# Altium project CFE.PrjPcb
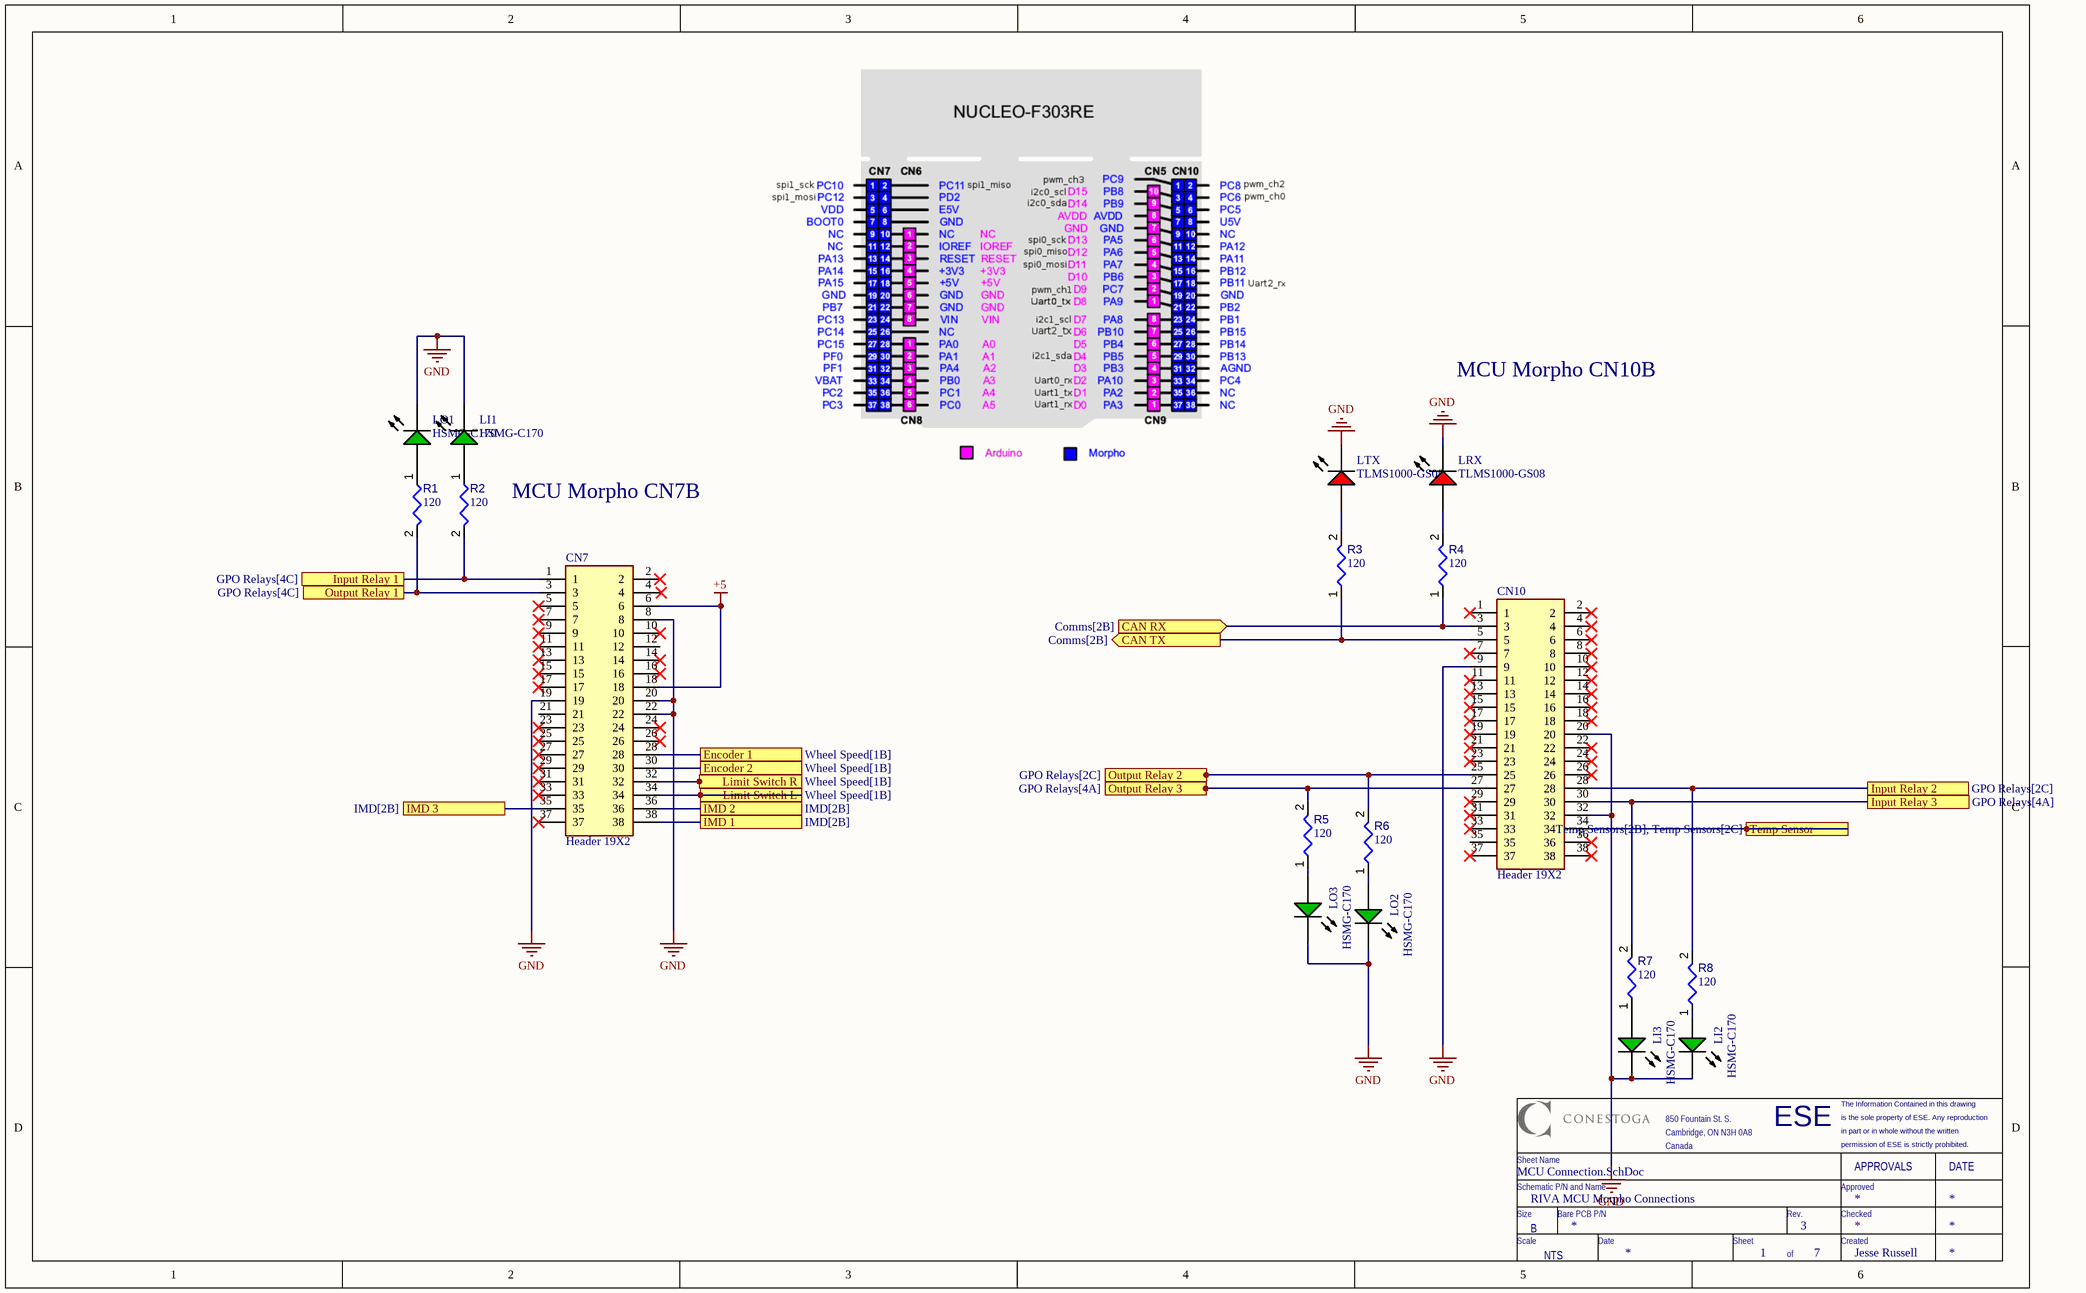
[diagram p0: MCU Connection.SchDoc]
7 sheets, 58 parts. Net scope: flat (ports and power ports of the same name join across sheets).
Board file: STM32 Sheild.PcbDoc
Sheets:
  MCU Connection.SchDoc
  Comms.SchDoc
  Power.SchDoc
  Temp Sensors.SchDoc
  GPO Relays.SchDoc
  Wheel Speed.SchDoc
  IMD.SchDoc

## Sheet MCU Connection.SchDoc: RIVA MCU Morpho Connections
size B; Engineer: Jesse Russell; Revision: 3; SheetNumber: 1; SheetTotal: 7

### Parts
CN7  Header 19X2  [2*19P]
CN10  Header 19X2  [2*19P]
LI1  HSMG-C170  [AVAG-HSMX-C170_V]
LI2  HSMG-C170  [AVAG-HSMX-C170_V]
LI3  HSMG-C170  [AVAG-HSMX-C170_V]
LO1  HSMG-C170  [AVAG-HSMX-C170_V]
LO2  HSMG-C170  [AVAG-HSMX-C170_V]
LO3  HSMG-C170  [AVAG-HSMX-C170_V]
LRX  TLMS1000-GS08  [VISH-TLMS1000_V]
LTX  TLMS1000-GS08  [VISH-TLMS1000_V]
R1  value 120  [RESC0603(1608)_L]  (hidden comment: Resistor 120R +/-5 % 0603 0.1 W)
R2  value 120  [RESC0603(1608)_L]  (hidden comment: Resistor 120R +/-5 % 0603 0.1 W)
R3  value 120  [RESC0603(1608)_L]  (hidden comment: Resistor 120R +/-5 % 0603 0.1 W)
R4  value 120  [RESC0603(1608)_L]  (hidden comment: Resistor 120R +/-5 % 0603 0.1 W)
R5  value 120  [RESC0603(1608)_L]  (hidden comment: Resistor 120R +/-5 % 0603 0.1 W)
R6  value 120  [RESC0603(1608)_L]  (hidden comment: Resistor 120R +/-5 % 0603 0.1 W)
R7  value 120  [RESC0603(1608)_L]  (hidden comment: Resistor 120R +/-5 % 0603 0.1 W)
R8  value 120  [RESC0603(1608)_L]  (hidden comment: Resistor 120R +/-5 % 0603 0.1 W)

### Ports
CAN RX (in, see Comms[2B]), CAN TX (out, see Comms[2B]), Encoder 1 (see Wheel Speed[1B]), Encoder 2 (see Wheel Speed[1B]), IMD 1 (see IMD[2B]), IMD 2 (see IMD[2B]), IMD 3 (see IMD[2B]), Input Relay 1 (see GPO Relays[4C]), Input Relay 2 (see GPO Relays[2C]), Input Relay 3 (see GPO Relays[4A]), Limit Switch L (see Wheel Speed[1B]), Limit Switch R (see Wheel Speed[1B]), Output Relay 1 (see GPO Relays[4C]), Output Relay 2 (see GPO Relays[2C]), Output Relay 3 (see GPO Relays[4A]), Temp Sensor (see Temp Sensors[2B], Temp Sensors[2C])

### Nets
+5: CN7.6 CN7.18
GND: CN7.8 CN7.19 CN7.20 CN7.22 CN10.9 CN10.20 CN10.32 LI1.2(K) LI2.2(K) LI3.2(K) LO1.2(K) LO2.2(K) LO3.2(K) LRX.2(K) LTX.2(K)
NetCN7_1: CN7.1 R2.2 ; port Input Relay 1
NetCN7_3: CN7.3 R1.2 ; port Output Relay 1
NetCN7_28: CN7.28 ; port Encoder 1
NetCN7_30: CN7.30 ; port Encoder 2
NetCN7_32: CN7.32 ; port Limit Switch R
NetCN7_34: CN7.34 ; port Limit Switch L
NetCN7_35: CN7.35 ; port IMD 3
NetCN7_36: CN7.36 ; port IMD 2
NetCN7_38: CN7.38 ; port IMD 1
NetCN10_3: CN10.3 R4.1 ; port CAN RX
NetCN10_5: CN10.5 R3.1 ; port CAN TX
NetCN10_25: CN10.25 R6.2 ; port Output Relay 2
NetCN10_27: CN10.27 R5.2 ; port Output Relay 3
NetCN10_28: CN10.28 R8.2 ; port Input Relay 2
NetCN10_30: CN10.30 R7.2 ; port Input Relay 3
NetCN10_34: CN10.34 ; port Temp Sensor
NetLI1_1: LI1.1(A) R2.1
NetLI2_1: LI2.1(A) R8.1
NetLI3_1: LI3.1(A) R7.1
NetLO1_1: LO1.1(A) R1.1
NetLO2_1: LO2.1(A) R6.1
NetLO3_1: LO3.1(A) R5.1
NetLRX_1: LRX.1(A) R4.2
NetLTX_1: LTX.1(A) R3.2

Not connected (* = marked no-connect by the designer): CN7 2* 4 5* 7* 9* 10* 11* 12 13* 14* 15* 16* 17* 21 23* 24* 25* 26* 27* 29* 31* 33* 37*; CN10 1* 2* 4* 6* 7* 8* 10* 11* 12* 13* 14* 15* 16* 17* 18* 19* 21* 22* 23* 24* 26* 29* 31* 33* 35 36* 37* 38*

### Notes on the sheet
- MCU Morpho CN10B
- MCU Morpho CN7B

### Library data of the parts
CN7 CN10 = SSW-119-01-T-D: Connector; Manufacturer_Name: SAMTEC
LI1-LI3 LO1-LO3 = CMP-2000-05062-1: Chip LED, Green, 2.2 V, -40 to 85 degC, 2-Pin SMD, Pb-Free, Tape and Reel; Manufacturer: Avago; No. of Pins: 2; Peak Wavelength: 570nm; SVHC: NoSVHC(16-Jun-2014); Dominant Wavelength: 572nm; Forward Current If: 20mA; Viewing Angle: 170deg; Lens Shape: Rectangular; PIV Max: 5V; External Width: 1.25mm; LED Type: Standard; External Depth: 0.8mm; Opto Mounting Orientation: Top; Luminous Intensity: 15mcd; Luminous Intensity Min: 4mcd; Forward Voltage VF Max: 2.6V; External Length / Height: 2mm; Bulb Size: 1.25mmx1.4mm; Light Area Height: 1mm; Voltage Vf Typ: 2.2V
LRX LTX = CMP-2000-07254-1: Low Current LED, 40 mW, 1.8 V, -40 to 100 degC, 2-Pin SMD (0603), RoHS, Tape and Reel; Manufacturer: Vishay; Lens Shape: Rectangular; Automotive Qualification Standard: AEC-Q100; Wavelength Typ: 636nm; SVHC: ToBeAdvised; LED Colour: Red; Bulb Size: 1.6mmx0.8mm; Forward Voltage: 1.8V; Luminous Intensity: 4mcd; Forward Current If: 2mA; Viewing Angle: 80°
R1-R8 = CMP-009-00176-3: Chip Resistor, 120 Ohms, +/-5 %, 0.1 W, -55 to 155 degC, 0603; Power: 100mW; Tolerance: 5%

## Sheet Comms.SchDoc: Communication (R-Pi, RS232, CANBUS)
size B; Engineer: Jesse Russell; Organization: Conestoga Collage; Revision: 4; SheetNumber: 2; SheetTotal: 7
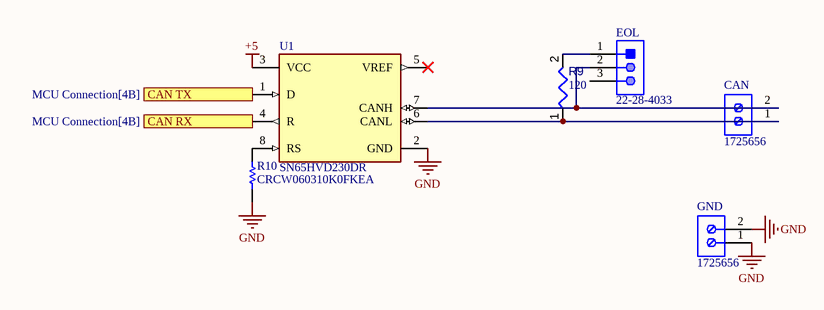
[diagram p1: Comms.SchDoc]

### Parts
CAN  1725656  [PHOE-1725656-2]
EOL  22-28-4033  [MOLX-22-28-4033_V]
GND  1725656  [PHOE-1725656-2]
R9  value 120  [RESC0603(1608)_L]  (hidden comment: Resistor 120R +/-5 % 0603 0.1 W)
R10  CRCW060310K0FKEA  [RESC1609X50X30NL8T20]
U1  SN65HVD230DR  [FP-D0008A-IPC_A]

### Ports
CAN RX (in, see MCU Connection[4B]), CAN TX (out, see MCU Connection[4B])

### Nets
+5: U1.3(VCC)
GND: GND.1 GND.2 R10.1 U1.2(GND)
NetCAN_1: CAN.1 R9.1 U1.6(CANL)
NetCAN_2: CAN.2 EOL.2 U1.7(CANH)
NetCN10_3: U1.4(R) ; port CAN RX
NetCN10_5: U1.1(D) ; port CAN TX
NetEOL_1: EOL.1 R9.2
NetR10_2: R10.2 U1.8(RS)

Not connected (* = marked no-connect by the designer): EOL 3; U1 5(VREF)*

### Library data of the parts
CAN GND = CMP-2000-05299-1: Male Header, Pitch 2.54 mm, 1 x 2 Position, Height 9 mm, Tail Length 3.5 mm; Manufacturer: Phoenix Contact; Number of contacts: 2; Content: 250pc(s); Pitch: 2.54mm; Industrial packaging: Yes
EOL = CMP-1676-00001-5: Male Header, Pitch 2.54 mm, 1 x 3 Position, Height 8.38 mm, Tail Length 3.18 mm, RoHS, Bulk; Manufacturer: Molex; Rows: 1; Voltage Rating: 250 V; Current Rating: 4 A
R9 = CMP-009-00176-3: as R1 on sheet MCU Connection
R10 = CMP-1666-00005-4: Chip Resistor, 10 KOhm, +/- 1%, 100 mW, -55 to 155 degC, 0603 (1608 Metric), RoHS, Tape and Reel; Manufacturer: Vishay Semiconductor; Voltage Rating: 75 V
U1 = CMP-0315-00015-3: IC TRANSCEIVER HALF 1/1 8SOIC; Number of Transceivers: 1; Operating Supply Voltage: 3.3V; Number of I/Os: 2; Max Supply Current: 17mA; Max Supply Voltage: 3.6V; Min Supply Voltage: 3V; Data Rate: 1Mbps

## Sheet Power.SchDoc
size A4; SheetNumber: 3; SheetTotal: 7
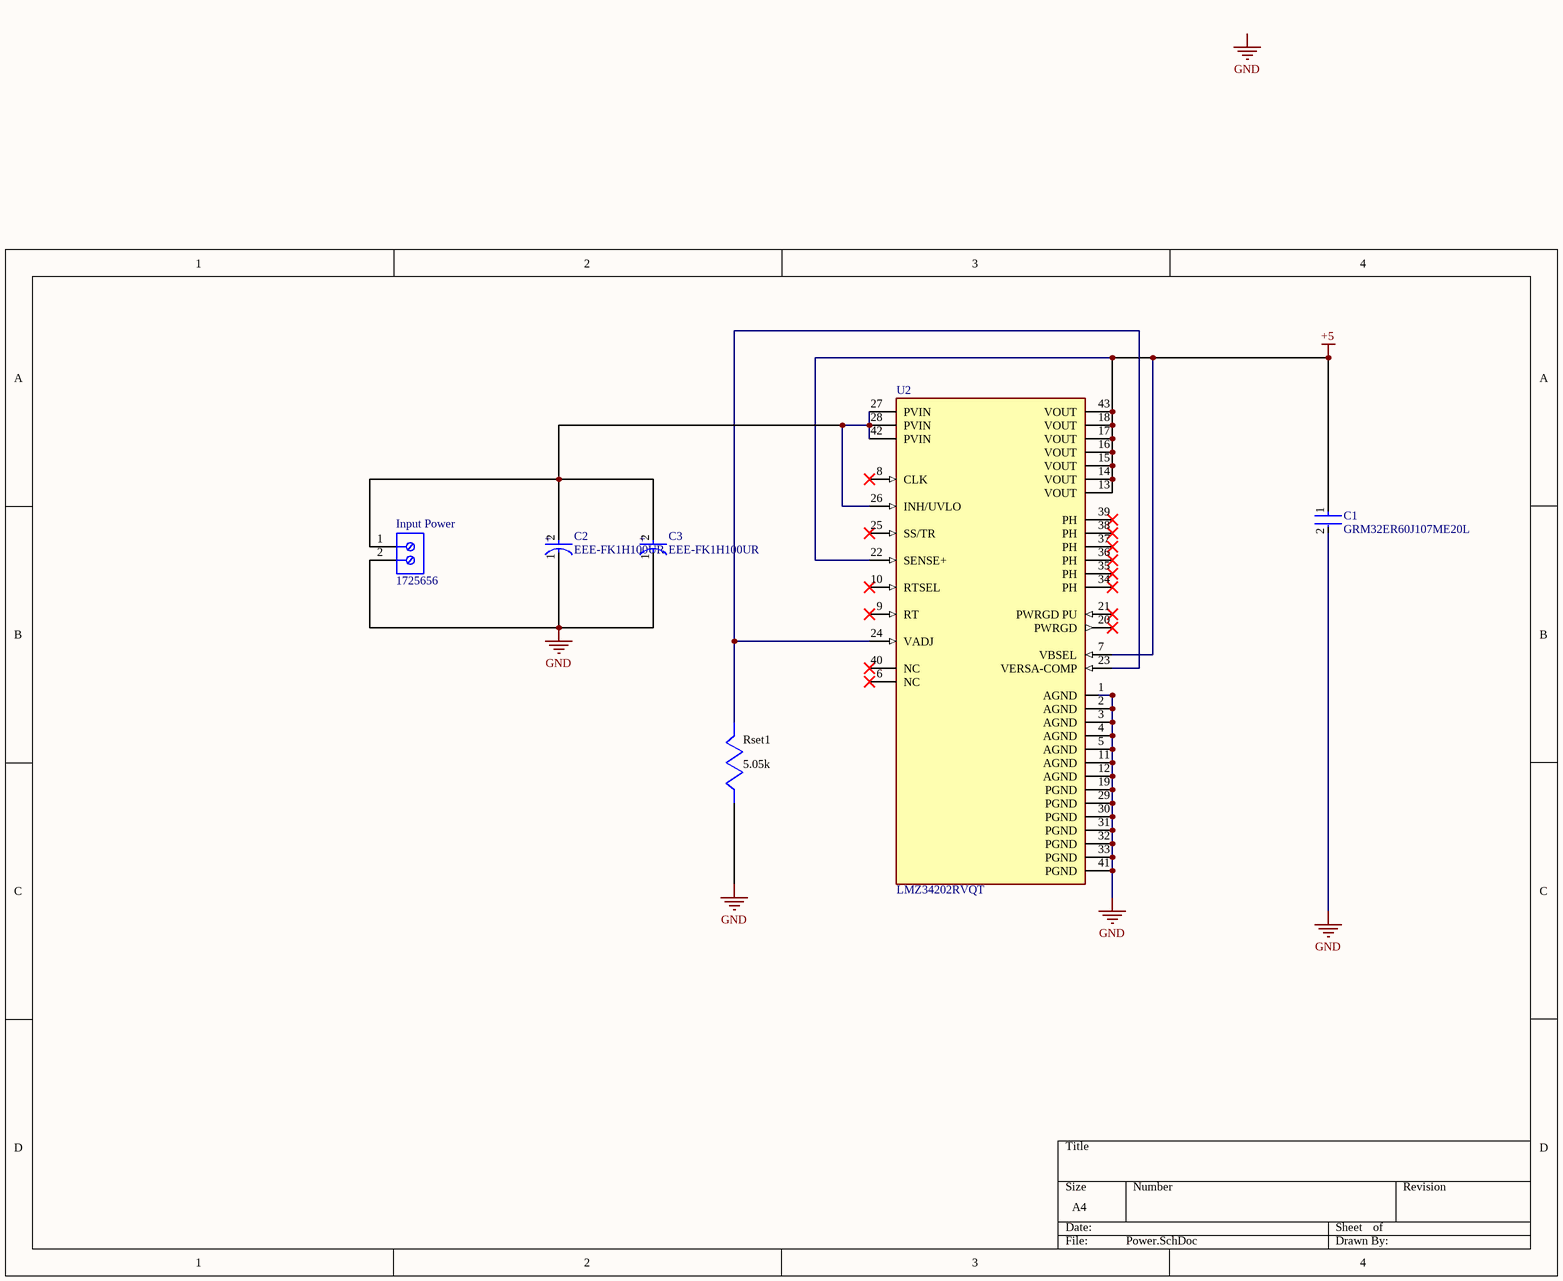
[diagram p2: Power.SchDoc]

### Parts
C1  GRM32ER60J107ME20L  [FP-GRM32-0_3-MFG]
C2  EEE-FK1H100UR  [FP-FKC-MFG]
C3  EEE-FK1H100UR  [FP-FKC-MFG]
Input_Power  1725656  [PHOE-1725656-2]
Rset1  value 5.05k  (hidden comment: CUSTOM1)
U2  LMZ34202RVQT  [FP-RVQ0043E-MFG]

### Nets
+5: C1.1 U2.7(VBSEL) U2.13(VOUT) U2.14(VOUT) U2.15(VOUT) U2.16(VOUT) U2.17(VOUT) U2.18(VOUT) U2.22(SENSE+) U2.43(VOUT)
GND: C1.2 C2.1(C) C3.1(C) Input_Power.2 Rset1.1 U2.1(AGND) U2.2(AGND) U2.3(AGND) U2.4(AGND) U2.5(AGND) U2.11(AGND) U2.12(AGND) U2.19(PGND) U2.29(PGND) U2.30(PGND) U2.31(PGND) U2.32(PGND) U2.33(PGND) U2.41(PGND)
NetC2_2: C2.2(A) C3.2(A) Input_Power.1 U2.26(INH/UVLO) U2.27(PVIN) U2.28(PVIN) U2.42(PVIN)
NetRset1_2: Rset1.2 U2.23(VERSA-COMP) U2.24(VADJ)

Not connected (* = marked no-connect by the designer): U2 6(NC)* 8(CLK)* 9(RT)* 10(RTSEL)* 20(PWRGD)* 21(PWRGD_PU)* 25(SS/TR)* 34(PH)* 35(PH)* 36(PH)* 37(PH)* 38(PH)* 39(PH)* 40(NC)*

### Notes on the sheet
- Labels drawn without touching a wire or pin: GND

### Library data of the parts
C1 = CMP-2000-05259-2: CAP CER 100UF 6.3V X5R 1210; 3DS Part Number: 220-00002; Manufacturer: Murata; Description: Chip Multilayer Ceramic Capacitors for General; Temperature Coefficient: 15%; Material: Ceramic; Tolerance: 20%
C2 C3 = CMP-05427-000030-1: CAP ALUM 10UF 20% 50V SMD; Impedance: 1.52R; Ripple Current (AC): 85mA; Life (Hours): 2000Hour; Leakage Current: 3uA; Dielectric Material: Aluminium
Input_Power = CMP-2000-05299-1: as CAN on sheet Comms
Rset1 = CUSTOM1: Manufacturer Name: CUSTOM
U2 = CMP-04918-000024-1: DC DC CONVERTER 2.5-7.5V 2A; Manufacturer: Texas Instruments; Output Type: AdjustableProgrammable; Max Junction Temp: +125°C; Max Duty Cycle: 90%; Min Supply Voltage: 4.5V; Switching Frequency: 300-1000kHz; Nominal Supply Current: 0.6mA; Max Supply Voltage: 42V; Switching Topology: Buck,Buck-Boost; Standoff Height: 0mm; Description: Non-Isolated PoL Module DC DC Converter 1 Output 2.5 ~ 7.5V    2A 4.5V - 42V Input; Number Of Outputs: 1

## Sheet Temp Sensors.SchDoc
size A4; SheetNumber: 4; SheetTotal: 7
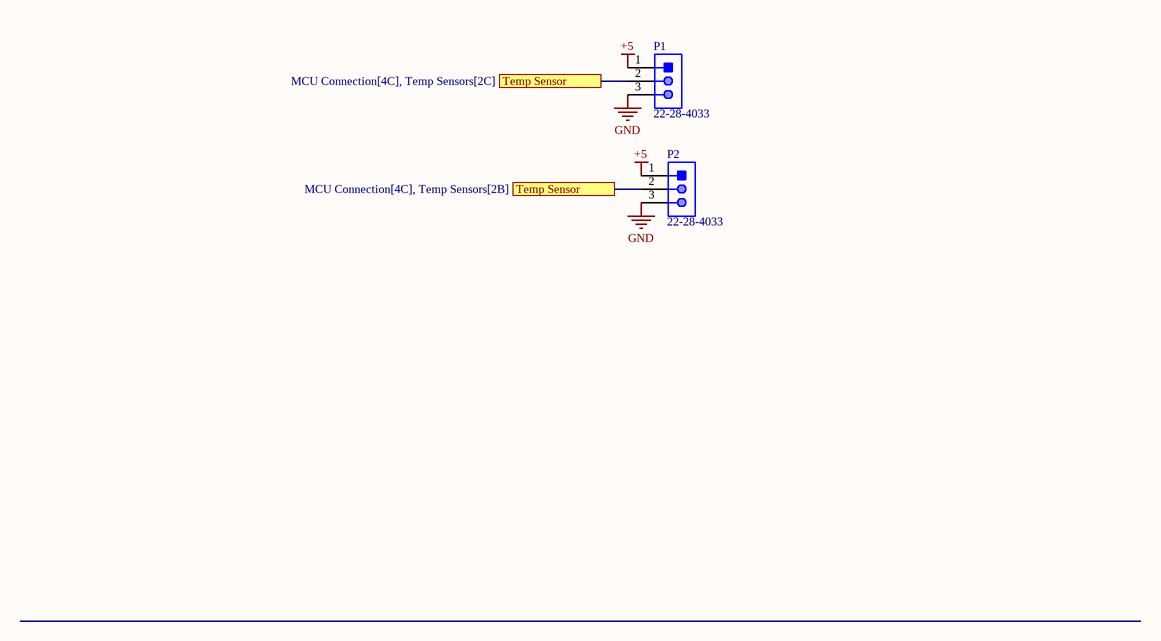
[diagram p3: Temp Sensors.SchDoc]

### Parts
P1  22-28-4033  [MOLX-22-28-4033_V]
P2  22-28-4033  [MOLX-22-28-4033_V]

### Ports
Temp Sensor (see MCU Connection[4C], Temp Sensors[2B]), Temp Sensor (see MCU Connection[4C], Temp Sensors[2C])

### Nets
+5: P1.1 P2.1
GND: P1.3 P2.3
NetCN10_34: P1.2 P2.2 ; port Temp Sensor

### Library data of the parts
P1 P2 = CMP-1676-00001-5: as EOL on sheet Comms

## Sheet GPO Relays.SchDoc
size A4; SheetNumber: 5; SheetTotal: 7
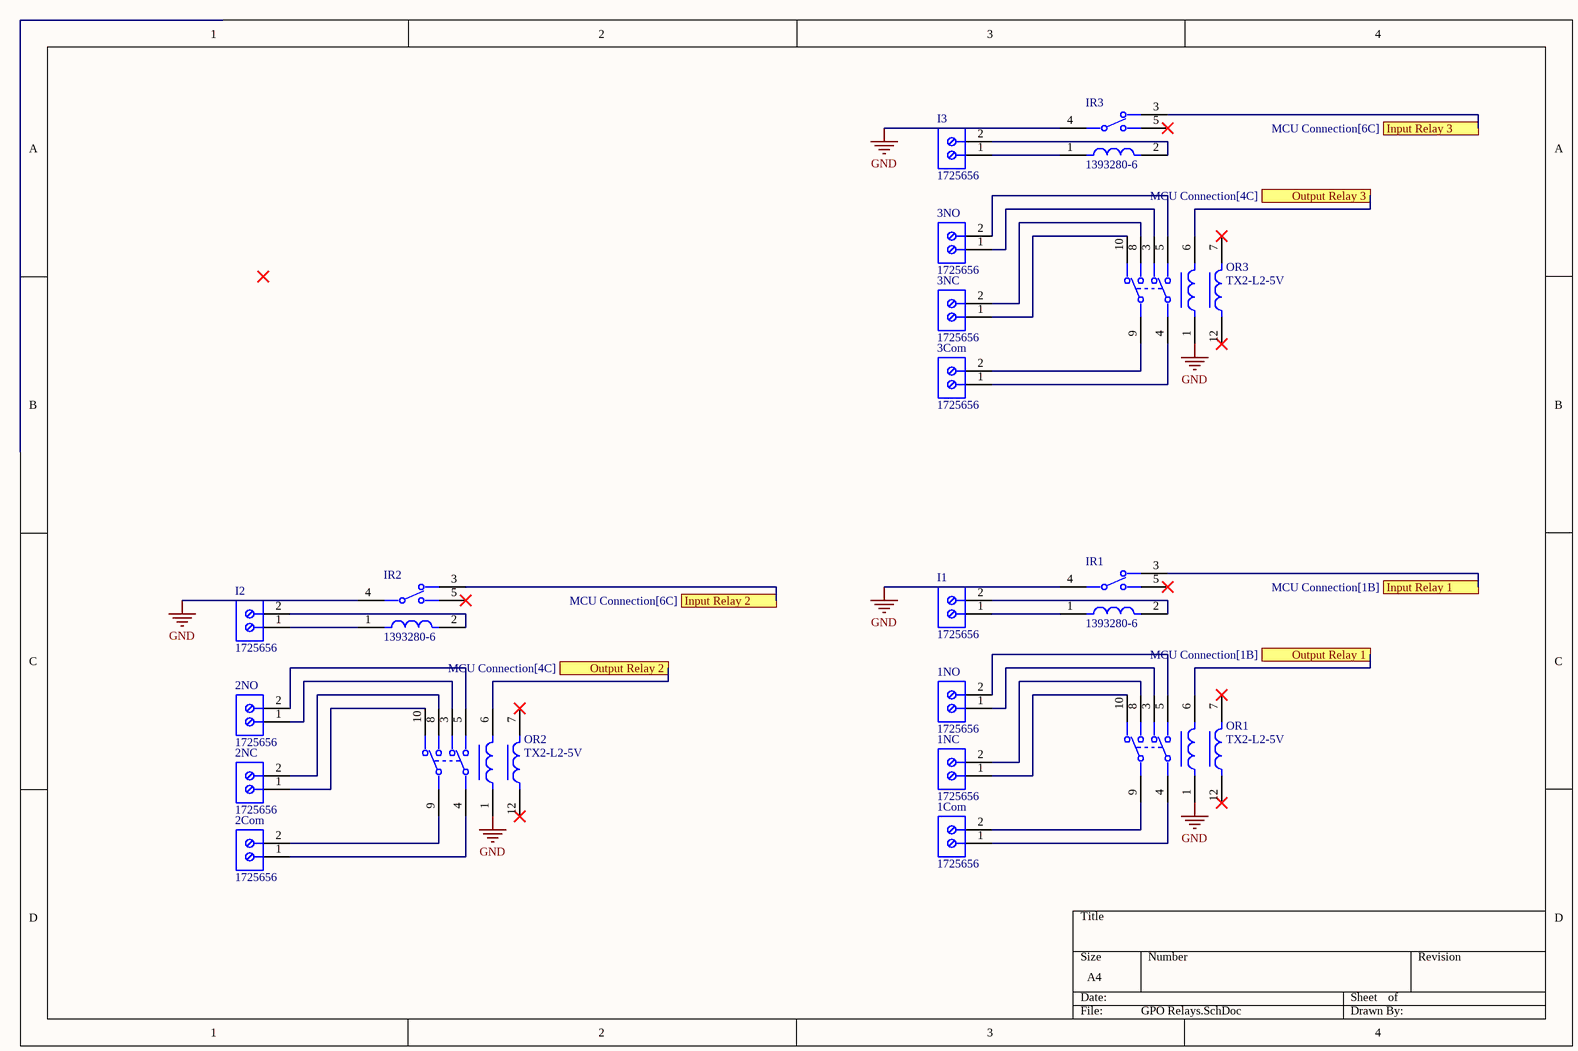
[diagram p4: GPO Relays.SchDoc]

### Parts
1Com  1725656  [PHOE-1725656-2]
1NC  1725656  [PHOE-1725656-2]
1NO  1725656  [PHOE-1725656-2]
2Com  1725656  [PHOE-1725656-2]
2NC  1725656  [PHOE-1725656-2]
2NO  1725656  [PHOE-1725656-2]
3Com  1725656  [PHOE-1725656-2]
3NC  1725656  [PHOE-1725656-2]
3NO  1725656  [PHOE-1725656-2]
I1  1725656  [PHOE-1725656-2]
I2  1725656  [PHOE-1725656-2]
I3  1725656  [PHOE-1725656-2]
IR1  1393280-6  [FP-1393280-6-MFG]
IR2  1393280-6  [FP-1393280-6-MFG]
IR3  1393280-6  [FP-1393280-6-MFG]
OR1  TX2-L2-5V  [FP-TX2-L2-5V-MFG]
OR2  TX2-L2-5V  [FP-TX2-L2-5V-MFG]
OR3  TX2-L2-5V  [FP-TX2-L2-5V-MFG]

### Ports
Input Relay 1 (see MCU Connection[1B]), Input Relay 2 (see MCU Connection[6C]), Input Relay 3 (see MCU Connection[6C]), Output Relay 1 (see MCU Connection[1B]), Output Relay 2 (see MCU Connection[4C]), Output Relay 3 (see MCU Connection[4C])

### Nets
GND: IR1.4 IR2.4 IR3.4 OR1.1(SET+) OR2.1(SET+) OR3.1(SET+)
Net1Com_1: 1Com.1 OR1.4
Net1Com_2: 1Com.2 OR1.9
Net1NC_1: 1NC.1 OR1.10
Net1NC_2: 1NC.2 OR1.8
Net1NO_1: 1NO.1 OR1.3
Net1NO_2: 1NO.2 OR1.5
Net2Com_1: 2Com.1 OR2.4
Net2Com_2: 2Com.2 OR2.9
Net2NC_1: 2NC.1 OR2.10
Net2NC_2: 2NC.2 OR2.8
Net2NO_1: 2NO.1 OR2.3
Net2NO_2: 2NO.2 OR2.5
Net3Com_1: 3Com.1 OR3.4
Net3Com_2: 3Com.2 OR3.9
Net3NC_1: 3NC.1 OR3.10
Net3NC_2: 3NC.2 OR3.8
Net3NO_1: 3NO.1 OR3.3
Net3NO_2: 3NO.2 OR3.5
NetCN7_1: IR1.3 ; port Input Relay 1
NetCN7_3: OR1.6(SET-) ; port Output Relay 1
NetCN10_25: OR2.6(SET-) ; port Output Relay 2
NetCN10_27: OR3.6(SET-) ; port Output Relay 3
NetCN10_28: IR2.3 ; port Input Relay 2
NetCN10_30: IR3.3 ; port Input Relay 3
NetI1_1: I1.1 IR1.1
NetI1_2: I1.2 IR1.2
NetI2_1: I2.1 IR2.1
NetI2_2: I2.2 IR2.2
NetI3_1: I3.1 IR3.1
NetI3_2: I3.2 IR3.2

Not connected (* = marked no-connect by the designer): IR1 5*; IR2 5*; IR3 5*; OR1 7(RESET-)* 12(RESET+)*; OR2 7(RESET-)* 12(RESET+)*; OR3 7(RESET-)* 12(RESET+)*

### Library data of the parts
1Com 1NC 1NO 2Com 2NC 2NO 3Com 3NC 3NO I1-I3 = CMP-2000-05299-1: as CAN on sheet Comms
IR1-IR3 = CMP-03395-000123-1: Electromechanical Relay 12VDC 254Ohm 40A SPDT (12.9x12x9.9)mm THT Power Relay; Manufacturer: TE Connectivity; Coil Voltage: 12V; Number Of Contacts: 1; Coil Resistance: 254Ω; Coil Type: Non-Latching; Standoff Height: 0.3mm; Current Rating: 30A; Coil Power: 567mW
OR1-OR3 = CMP-00287-39525588-1: TX2-L2-5V Telecom Relay DPDT (2 Form C) Latching Double Coil 5VDC 2A Through Hole 125 Ohm; Hole Diameter: 1mm; Operate Time: 4ms; Coil Voltage (DC): 5V; Voltage Rating (DC): 220V; Power Rating: 60W; Coil Power: 200mW; Approvals: CSA, UL; Test Voltage: 2kV; Number of Poles: 2; Pitch: 2.54mm; Ratings: IP67; Coil Type: Latching, Dual Coil; Coil Current: 40mA; Insertion Loss (dB): 0.8dB; Coil Resistance: 125Ω

## Sheet Wheel Speed.SchDoc
size A4; SheetNumber: 6; SheetTotal: 7
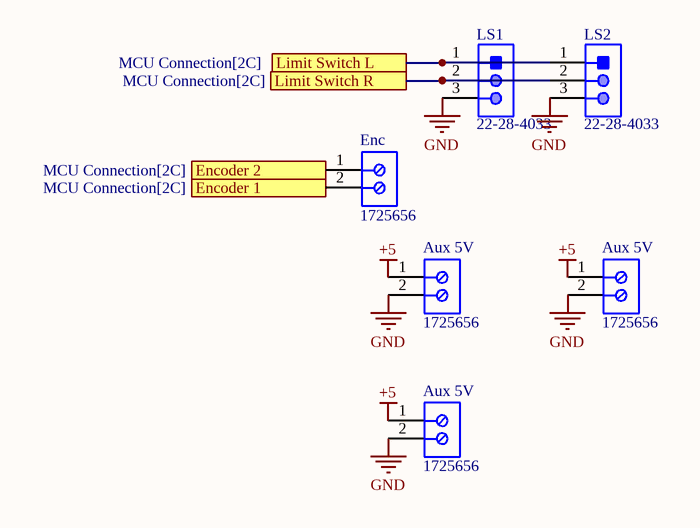
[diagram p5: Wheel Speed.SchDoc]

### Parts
(Parts that share a designator on the sheet are numbered #1, #2 ... from top to bottom, then left to right.)
Aux_5V#1  1725656  [PHOE-1725656-2]
Aux_5V#2  1725656  [PHOE-1725656-2]
Aux_5V#3  1725656  [PHOE-1725656-2]
Enc  1725656  [PHOE-1725656-2]
LS1  22-28-4033  [MOLX-22-28-4033_V]
LS2  22-28-4033  [MOLX-22-28-4033_V]

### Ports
Encoder 1 (see MCU Connection[2C]), Encoder 2 (see MCU Connection[2C]), Limit Switch L (see MCU Connection[2C]), Limit Switch R (see MCU Connection[2C])

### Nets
+5: Aux_5V#1.1 Aux_5V#2.1 Aux_5V#3.1
GND: Aux_5V#1.2 Aux_5V#2.2 Aux_5V#3.2 LS1.3 LS2.3
NetCN7_28: Enc.2 ; port Encoder 1
NetCN7_30: Enc.1 ; port Encoder 2
NetCN7_32: LS1.2 LS2.2 ; port Limit Switch R
NetCN7_34: LS1.1 LS2.1 ; port Limit Switch L

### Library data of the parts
Aux_5V#1-Aux_5V#3 Enc = CMP-2000-05299-1: as CAN on sheet Comms
LS1 LS2 = CMP-1676-00001-5: as EOL on sheet Comms

## Sheet IMD.SchDoc
size A4; SheetNumber: 7; SheetTotal: 7
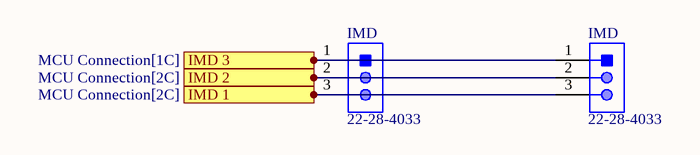
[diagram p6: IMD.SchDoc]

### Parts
(Parts that share a designator on the sheet are numbered #1, #2 ... from top to bottom, then left to right.)
IMD#1  22-28-4033  [MOLX-22-28-4033_V]
IMD#2  22-28-4033  [MOLX-22-28-4033_V]

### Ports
IMD 1 (see MCU Connection[2C]), IMD 2 (see MCU Connection[2C]), IMD 3 (see MCU Connection[1C])

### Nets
NetCN7_35: IMD#1.1 IMD#2.1 ; port IMD 3
NetCN7_36: IMD#1.2 IMD#2.2 ; port IMD 2
NetCN7_38: IMD#1.3 IMD#2.3 ; port IMD 1

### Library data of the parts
IMD#1 IMD#2 = CMP-1676-00001-5: as EOL on sheet Comms

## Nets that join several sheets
+5: MCU Connection (CN7.6 CN7.18), Comms (U1.3), Power (10 pins), Temp Sensors (P1.1 P2.1), Wheel Speed (Aux_5V#1.1 Aux_5V#2.1 Aux_5V#3.1)
GND: MCU Connection (15 pins), Comms (GND.1 GND.2 R10.1 U1.2), Power (19 pins), Temp Sensors (P1.3 P2.3), GPO Relays (6 pins), Wheel Speed (5 pins)
NetCN7_1: MCU Connection (CN7.1 R2.2), GPO Relays (IR1.3)
NetCN7_3: MCU Connection (CN7.3 R1.2), GPO Relays (OR1.6)
NetCN7_28: MCU Connection (CN7.28), Wheel Speed (Enc.2)
NetCN7_30: MCU Connection (CN7.30), Wheel Speed (Enc.1)
NetCN7_32: MCU Connection (CN7.32), Wheel Speed (LS1.2 LS2.2)
NetCN7_34: MCU Connection (CN7.34), Wheel Speed (LS1.1 LS2.1)
NetCN7_35: MCU Connection (CN7.35), IMD (IMD#1.1 IMD#2.1)
NetCN7_36: MCU Connection (CN7.36), IMD (IMD#1.2 IMD#2.2)
NetCN7_38: MCU Connection (CN7.38), IMD (IMD#1.3 IMD#2.3)
NetCN10_3: MCU Connection (CN10.3 R4.1), Comms (U1.4)
NetCN10_5: MCU Connection (CN10.5 R3.1), Comms (U1.1)
NetCN10_25: MCU Connection (CN10.25 R6.2), GPO Relays (OR2.6)
NetCN10_27: MCU Connection (CN10.27 R5.2), GPO Relays (OR3.6)
NetCN10_28: MCU Connection (CN10.28 R8.2), GPO Relays (IR2.3)
NetCN10_30: MCU Connection (CN10.30 R7.2), GPO Relays (IR3.3)
NetCN10_34: MCU Connection (CN10.34), Temp Sensors (P1.2 P2.2)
